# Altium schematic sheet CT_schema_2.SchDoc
size 379 x 228 mm
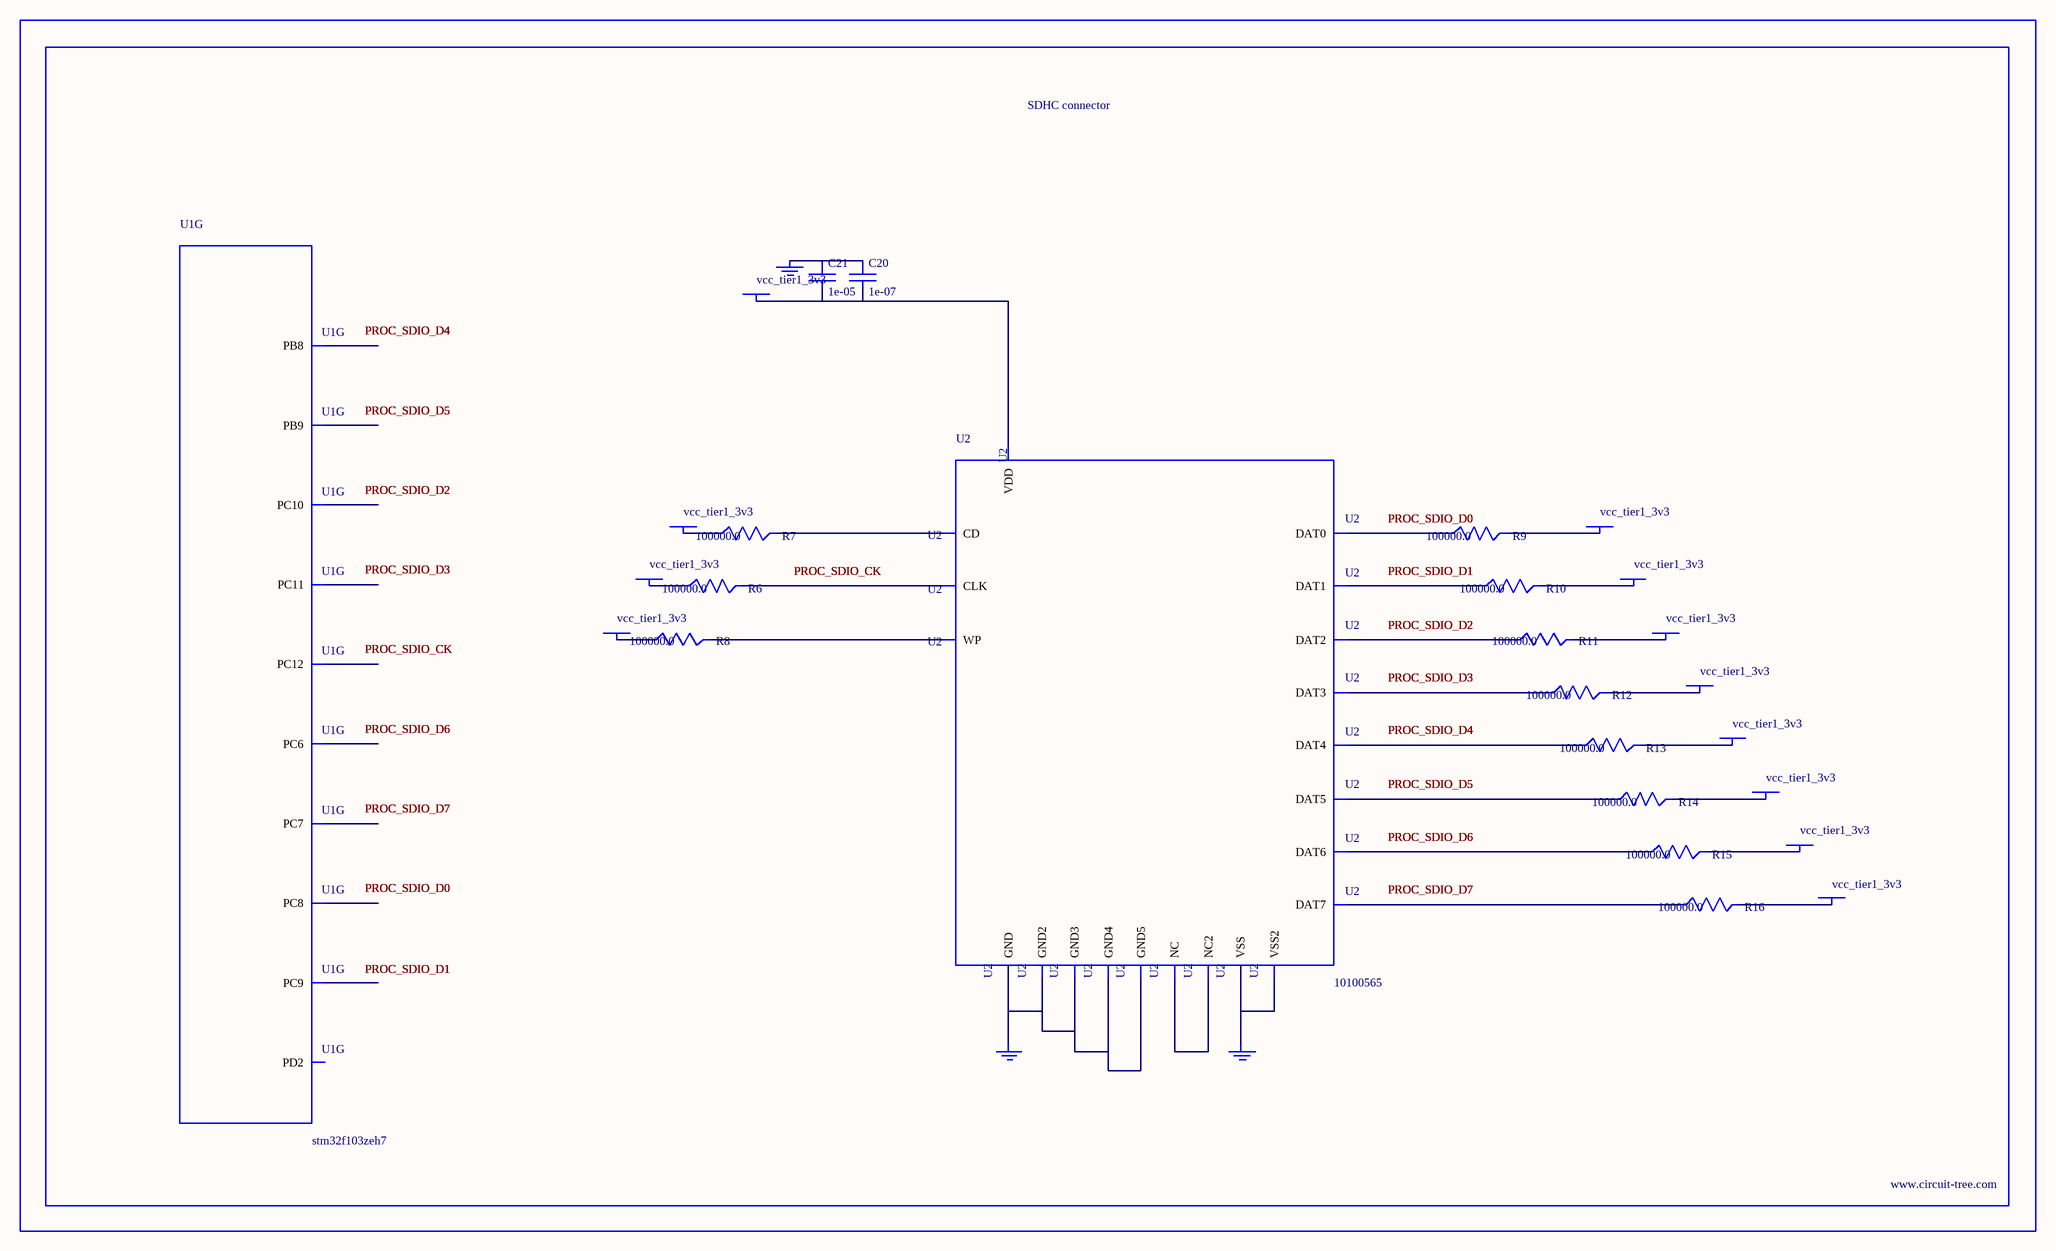
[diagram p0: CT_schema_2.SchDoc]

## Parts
BORDER1  (no value)
C20  1e-07  [C0402]
C21  1e-05  [C0805]
GND_INSTANCE_1_0  (no value)
GND_INSTANCE_1_1  (no value)
GND_INSTANCE_1_2  (no value)
POWER_INSTANCE_1_0  vcc_tier1_3v3
POWER_INSTANCE_1_1  vcc_tier1_3v3
POWER_INSTANCE_1_2  vcc_tier1_3v3
POWER_INSTANCE_1_3  vcc_tier1_3v3
POWER_INSTANCE_1_4  vcc_tier1_3v3
POWER_INSTANCE_1_5  vcc_tier1_3v3
POWER_INSTANCE_1_6  vcc_tier1_3v3
POWER_INSTANCE_1_7  vcc_tier1_3v3
POWER_INSTANCE_1_8  vcc_tier1_3v3
POWER_INSTANCE_1_9  vcc_tier1_3v3
POWER_INSTANCE_1_10  vcc_tier1_3v3
POWER_INSTANCE_1_11  vcc_tier1_3v3
R6  100000.0  [R0603]
R7  100000.0  [R0603]
R8  100000.0  [R0603]
R9  100000.0  [R0603]
R10  100000.0  [R0603]
R11  100000.0  [R0603]
R12  100000.0  [R0603]
R13  100000.0  [R0603]
R14  100000.0  [R0603]
R15  100000.0  [R0603]
R16  100000.0  [R0603]
U1  stm32f103zeh7  [LFBGA144]  (part G of 10)
U2  10100565  [10100565]

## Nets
NetC20_1: C20.1 C21.1 GND_INSTANCE_1_0.0(GND)
NetC20_2: C20.2 C21.2 POWER_INSTANCE_1_7.0(PWR) U2.9(VDD)
NetGND_INSTANCE_1_1_0: GND_INSTANCE_1_1.0(GND) U2.6(VSS) U2.10(VSS2)
NetGND_INSTANCE_1_2_0: GND_INSTANCE_1_2.0(GND) U2.12(GND) U2.16(GND2) U2.17(GND3) U2.20(GND4) U2.21(GND5)
NetPOWER_INSTANCE_1_0_0: POWER_INSTANCE_1_0.0(PWR) R8.1
NetPOWER_INSTANCE_1_1_0: POWER_INSTANCE_1_1.0(PWR) R7.1
NetPOWER_INSTANCE_1_2_0: POWER_INSTANCE_1_2.0(PWR) R10.2
NetPOWER_INSTANCE_1_3_0: POWER_INSTANCE_1_3.0(PWR) R9.2
NetPOWER_INSTANCE_1_4_0: POWER_INSTANCE_1_4.0(PWR) R16.2
NetPOWER_INSTANCE_1_5_0: POWER_INSTANCE_1_5.0(PWR) R15.2
NetPOWER_INSTANCE_1_6_0: POWER_INSTANCE_1_6.0(PWR) R6.1
NetPOWER_INSTANCE_1_8_0: POWER_INSTANCE_1_8.0(PWR) R14.2
NetPOWER_INSTANCE_1_9_0: POWER_INSTANCE_1_9.0(PWR) R13.2
NetPOWER_INSTANCE_1_10_0: POWER_INSTANCE_1_10.0(PWR) R12.2
NetPOWER_INSTANCE_1_11_0: POWER_INSTANCE_1_11.0(PWR) R11.2
NetR6_2: R6.2 U2.8(CLK)
NetR7_2: R7.2 U2.2(CD)
NetR8_2: R8.2 U2.1(WP)
NetR9_1: R9.1 U2.4(DAT0)
NetR10_1: R10.1 U2.3(DAT1)
NetR11_1: R11.1 U2.15(DAT2)
NetR12_1: R12.1 U2.14(DAT3)
NetR13_1: R13.1 U2.13(DAT4)
NetR14_1: R14.1 U2.11(DAT5)
NetR15_1: R15.1 U2.7(DAT6)
NetR16_1: R16.1 U2.5(DAT7)
NetU2_18: U2.18(NC) U2.19(NC2)

Not connected (* = marked no-connect by the designer): U1 B5(PB9) B10(PC11) B11(PC10) C5(PB8) C10(PC12) E9(PD2) E11(PC9) F11(PC8) F12(PC7) G12(PC6)

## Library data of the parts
BORDER1 = BORDER_PAGE1
C20 = C0402C104K3RACTU
C21 = C0805C106K8RACTU
GND_INSTANCE_1_0-GND_INSTANCE_1_2 = GND
POWER_INSTANCE_1_0-POWER_INSTANCE_1_11 = PWR
R6-R16 = RC0603JR-07100KL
